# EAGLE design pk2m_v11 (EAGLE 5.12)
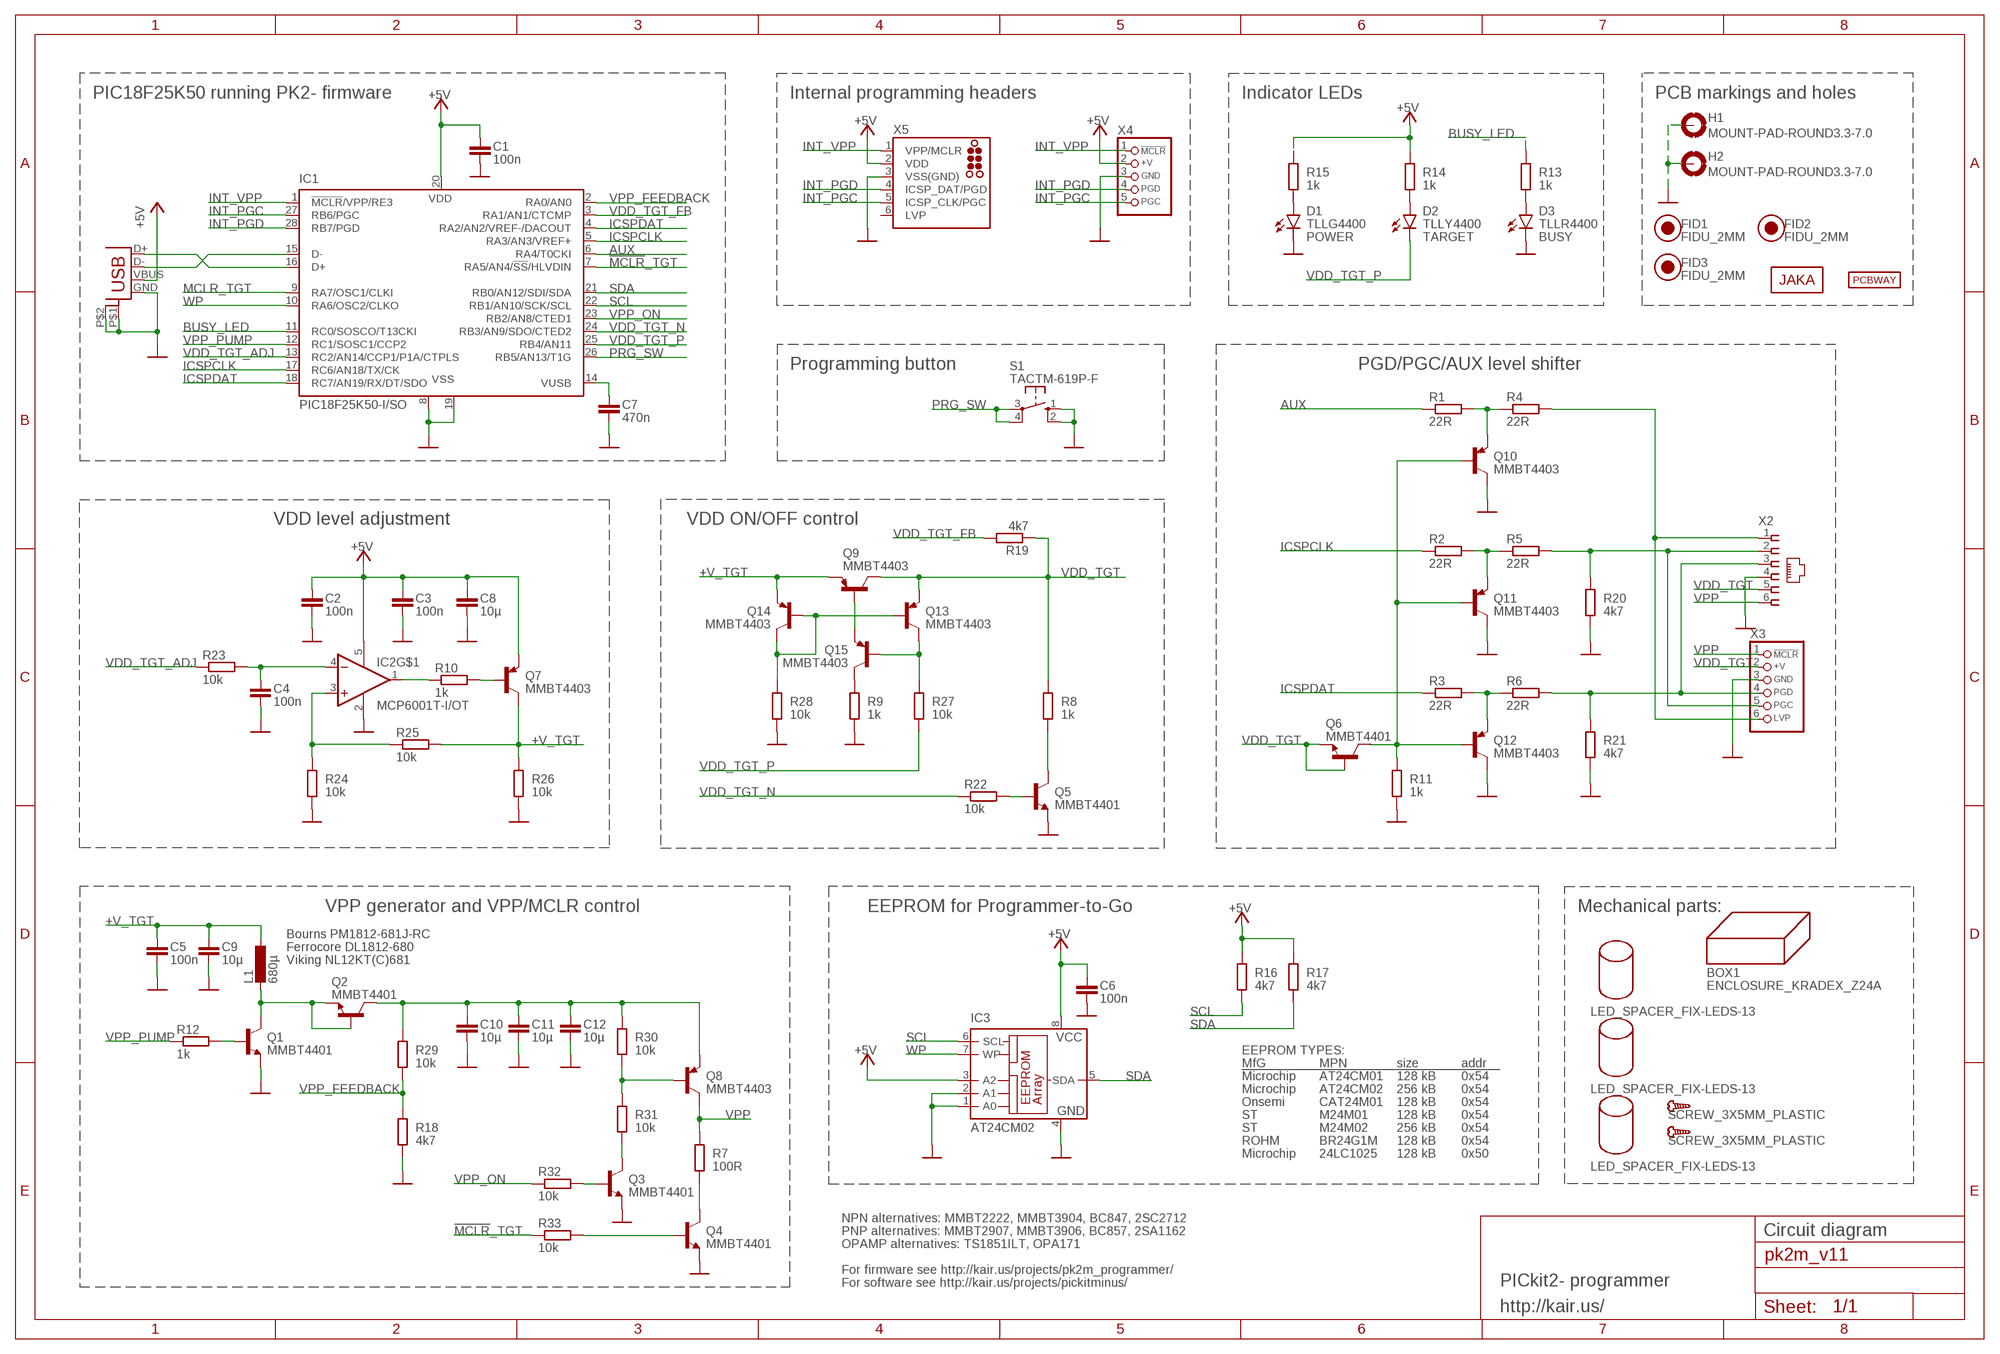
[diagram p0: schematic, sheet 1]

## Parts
BOX1  ENCLOSURE_KRADEX_Z24A  [KRADEX_Z24A]
C1  100n  C-EUC0805  [C0805]
C2  100n  C-EUC0805  [C0805]
C3  100n  C-EUC0805  [C0805]
C4  100n  C-EUC0805  [C0805]
C5  100n  C-EUC0805  [C0805]
C6  100n  C-EUC0805  [C0805]
C7  470n  C-EUC0805  [C0805]
C8  10µ  C-EUC0805  [C0805]
C9  10µ  C-EUC0805  [C0805]
C10  10µ  C-EUC0805  [C0805]
C11  10µ  C-EUC0805  [C0805]
C12  10µ  C-EUC0805  [C0805]
D1  TLLG4400  TLLG4400-LED-GREEN-3MM  [LED3MM]
D2  TLLY4400  TLLY4400-LED-YELLOW-3MM  [LED3MM]
D3  TLLR4400  TLLR4400-LED-RED-3MM  [LED3MM]
FID1  FIDU_2MM  [FIDU_2MM]
FID2  FIDU_2MM  [FIDU_2MM]
FID3  FIDU_2MM  [FIDU_2MM]
H1  MOUNT-PAD-ROUND3.3-7.0  [3,3-PAD-7,0]
H2  MOUNT-PAD-ROUND3.3-7.0  [3,3-PAD-7,0]
IC1  PIC18F25K50-I/SO  PIC18F2XK50-I/SO  [SO28W]
IC2  MCP6001T-I/OT  [SOT23-5]
IC3  AT24CM02  24AA1025T-I/SN  [SO08]
L1  680µ  L-EU_PM1812_BOURNS  [PM1812]
LOGO1  PCBWAY_LOGO_SILK_TINY  [PCBWAY_LOGO_SILK_TINY]
Q1  MMBT4401  MMBT4401LT1-NPN-SOT-23-BEC  [SOT-23]
Q2  MMBT4401  MMBT4401LT1-NPN-SOT-23-BEC  [SOT-23]
Q3  MMBT4401  MMBT4401LT1-NPN-SOT-23-BEC  [SOT-23]
Q4  MMBT4401  MMBT4401LT1-NPN-SOT-23-BEC  [SOT-23]
Q5  MMBT4401  MMBT4401LT1-NPN-SOT-23-BEC  [SOT-23]
Q6  MMBT4401  MMBT4401LT1-NPN-SOT-23-BEC  [SOT-23]
Q7  MMBT4403  MMBT4403LT1-PNP-SOT-23-BEC  [SOT-23]
Q8  MMBT4403  MMBT4403LT1-PNP-SOT-23-BEC  [SOT-23]
Q9  MMBT4403  MMBT4403LT1-PNP-SOT-23-BEC  [SOT-23]
Q10  MMBT4403  MMBT4403LT1-PNP-SOT-23-BEC  [SOT-23]
Q11  MMBT4403  MMBT4403LT1-PNP-SOT-23-BEC  [SOT-23]
Q12  MMBT4403  MMBT4403LT1-PNP-SOT-23-BEC  [SOT-23]
Q13  MMBT4403  MMBT4403LT1-PNP-SOT-23-BEC  [SOT-23]
Q14  MMBT4403  MMBT4403LT1-PNP-SOT-23-BEC  [SOT-23]
Q15  MMBT4403  MMBT4403LT1-PNP-SOT-23-BEC  [SOT-23]
R1  22R  R-EU_R0805  [R0805]
R2  22R  R-EU_R0805  [R0805]
R3  22R  R-EU_R0805  [R0805]
R4  22R  R-EU_R0805  [R0805]
R5  22R  R-EU_R0805  [R0805]
R6  22R  R-EU_R0805  [R0805]
R7  100R  R-EU_R0805  [R0805]
R8  1k  R-EU_R0805  [R0805]
R9  1k  R-EU_R0805  [R0805]
R10  1k  R-EU_R0805  [R0805]
R11  1k  R-EU_R0805  [R0805]
R12  1k  R-EU_R0805  [R0805]
R13  1k  R-EU_R0805  [R0805]
R14  1k  R-EU_R0805  [R0805]
R15  1k  R-EU_R0805  [R0805]
R16  4k7  R-EU_R0805  [R0805]
R17  4k7  R-EU_R0805  [R0805]
R18  4k7  R-EU_R0805  [R0805]
R19  4k7  R-EU_R0805  [R0805]
R20  4k7  R-EU_R0805  [R0805]
R21  4k7  R-EU_R0805  [R0805]
R22  10k  R-EU_R0805  [R0805]
R23  10k  R-EU_R0805  [R0805]
R24  10k  R-EU_R0805  [R0805]
R25  10k  R-EU_R0805  [R0805]
R26  10k  R-EU_R0805  [R0805]
R27  10k  R-EU_R0805  [R0805]
R28  10k  R-EU_R0805  [R0805]
R29  10k  R-EU_R0805  [R0805]
R30  10k  R-EU_R0805  [R0805]
R31  10k  R-EU_R0805  [R0805]
R32  10k  R-EU_R0805  [R0805]
R33  10k  R-EU_R0805  [R0805]
S1  TACTM-619P-F  10-XX  [B3F-10XX]
SPACER1  LED_SPACER_FIX-LEDS-13  [DUMMY]
SPACER2  LED_SPACER_FIX-LEDS-13  [DUMMY]
SPACER3  LED_SPACER_FIX-LEDS-13  [DUMMY]
U$1  JAKA_LOGO_SILK_NANO  [JAKA_SILK_NANO]
U$2  SCREW_3X5MM_PLASTIC  [DUMMY]
U$3  SCREW_3X5MM_PLASTIC  [DUMMY]
X1  USB_B_PTH  [USB-B-PTH]
X2  555165-1  [555165-1]
X3  CON_HEADER_PRG_PIC_W_LVP_ENDMARK  [HEADER_PRG_1X06_STAGGERED_ENDMARK]
X4  CON_HEADER_PRG_PIC_ICSPSTAG  [HEADER_PRG_1X05_STAGGERED]
X5  TC2030-MCP-NL-JKA  [TC2030-MCP-NL-JKA]

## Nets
!MCLR!_TGT: IC1.7(RA5/AN4/!SS!/HLVDIN) R33.1
+5V [power]: C1.1 C2.1 C3.1 C6.1 C8.1 IC1.20(VDD) IC2.5(V+) IC3.3(A2) IC3.8(VCC) Q7.2(E) R14.2 R15.2 R16.2 R17.2 X1.VBUS X4.2(+V) X5.2(VDD)
+V_TGT [power]: C5.1 C9.1 L1.1 Q7.3(C) Q9.2(E) Q14.2(E) R25.2 R26.2
AUX: IC1.6(RA4/T0CKI) R1.1
BUSY_LED: IC1.11(RC0/SOSCO/T13CKI) R13.2
GND [power]: C1.2 C2.2 C3.2 C4.2 C5.2 C6.2 C7.2 C8.2 C9.2 C10.2 C11.2 C12.2 D1.K D3.K H1.B3,3(MOUNT) H2.B3,3(MOUNT) IC1.8(VSS) IC1.19(VSS) IC2.2(V-) IC3.1(A0) IC3.2(A1) IC3.4(GND) Q1.2(E) Q3.2(E) Q4.2(E) Q5.2(E) Q10.3(C) Q11.3(C) Q12.3(C) R9.1 R11.1 R18.1 R20.1 R21.1 R24.1 R26.1 R28.1 S1.1(S) S1.2(S1) X1.GND X1.P$1(SHIELD) X1.P$2(SHIELD1) X2.4 X3.3(GND) X4.3(GND) X5.3(VSS(GND))
ICSPCLK: IC1.5(RA3/AN3/VREF+) IC1.17(RC6/AN18/TX/CK) R2.1
ICSPDAT: IC1.4(RA2/AN2/VREF-/DACOUT) IC1.18(RC7/AN19/RX/DT/SDO) R3.1
INT_PGC: IC1.27(RB6/PGC) X4.5(PGC) X5.5(ICSP_CLK/PGC)
INT_PGD: IC1.28(RB7/PGD) X4.4(PGD) X5.4(ICSP_DAT/PGD)
INT_VPP: IC1.1(!MCLR!/VPP/RE3) X4.1(/MCLR) X5.1(VPP/MCLR)
MCLR_TGT: IC1.9(RA7/OSC1/CLKI)
N$1 [power]: C7.1 IC1.14(VUSB)
N$2: D3.A R13.1
N$3: D2.A R14.1
N$4: D1.A R15.1
N$5: IC2.1(OUT) R10.1
N$6: Q13.1(B) Q14.1(B) Q14.3(C) R28.2
N$7 [USB]: IC1.16(D+) X1.D+
N$8 [USB]: IC1.15(D-) X1.D-
N$9: C4.1 IC2.4(-IN) R23.2
N$10: IC2.3(+IN) R24.2 R25.1
N$11: Q9.1(B) Q15.2(E)
N$12: Q7.1(B) R10.2
N$14: Q5.1(B) R22.2
N$15: Q3.1(B) R32.2
N$16: L1.2 Q1.3(C) Q2.1(B) Q2.2(E)
N$17: Q5.3(C) R8.1
N$18: Q1.1(B) R12.2
N$19: Q4.1(B) R33.2
N$20: Q12.2(E) R3.2 R6.1
N$21: C10.1 C11.1 C12.1 Q2.3(C) Q8.2(E) R29.2 R30.2
N$22: R6.2 R21.2 X2.3 X3.4(PGD)
N$23: Q8.1(B) R30.1 R31.2
N$24: Q4.3(C) R7.1
N$25: Q13.3(C) Q15.1(B) R27.2
N$26: Q3.3(C) R31.1
N$27: Q15.3(C) R9.2
N$28: Q11.2(E) R2.2 R5.1
N$29: R5.2 R20.2 X2.2 X3.5(PGC)
N$30: Q6.3(C) Q10.1(B) Q11.1(B) Q12.1(B) R11.2
N$31: Q10.2(E) R1.2 R4.1
N$32: R4.2 X2.1 X3.6(LVP)
PRG_SW: IC1.26(RB5/AN13/T1G) S1.3(P) S1.4(P1)
SCL: IC1.22(RB1/AN10/SCK/SCL) IC3.6(SCL) R16.1
SDA: IC1.21(RB0/AN12/SDI/SDA) IC3.5(SDA) R17.1
VDD_TGT [power]: Q6.1(B) Q6.2(E) Q9.3(C) Q13.2(E) R8.2 R19.1 X2.5 X3.2(+V)
VDD_TGT_ADJ: IC1.13(RC2/AN14/CCP1/P1A/CTPLS) R23.1
VDD_TGT_FB: IC1.3(RA1/AN1/CTCMP) R19.2
VDD_TGT_N: IC1.24(RB3/AN9/SDO/CTED2) R22.1
VDD_TGT_P: D2.K IC1.25(RB4/AN11) R27.1
VPP: Q8.3(C) R7.2 X2.6 X3.1(/MCLR)
VPP_FEEDBACK: IC1.2(RA0/AN0) R18.2 R29.1
VPP_ON: IC1.23(RB2/AN8/CTED1) R32.1
VPP_PUMP: IC1.12(RC1/SOSC1/CCP2) R12.1
WP: IC1.10(RA6/OSC2/CLKO) IC3.7(WP)
Unconnected: X5.6(LVP)

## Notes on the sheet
- PIC18F25K50 running PK2- firmware | Internal programming headers | Indicator LEDs | PCB markings and holes
- POWER | TARGET | BUSY
- Programming button | PGD/PGC/AUX level shifter
- VDD level adjustment | VDD ON/OFF control
- VPP generator and VPP/MCLR control | EEPROM for Programmer-to-Go | Mechanical parts:
- Bourns PM1812-681J-RC
- Ferrocore DL1812-680
- Viking NL12KT(C)681
- EEPROM TYPES:
- MfG | MPN | size | addr
- Microchip | AT24CM01 | 128 kB | 0x54
- Microchip | AT24CM02 | 256 kB | 0x54
- Onsemi | CAT24M01 | 128 kB | 0x54
- ST | M24M01 | 128 kB | 0x54
- ST | M24M02 | 256 kB | 0x54
- ROHM | BR24G1M | 128 kB | 0x54
- Microchip | 24LC1025 | 128 kB | 0x50
- NPN alternatives: MMBT2222, MMBT3904, BC847, 2SC2712
- PNP alternatives: MMBT2907, MMBT3906, BC857, 2SA1162 | Circuit diagram
- OPAMP alternatives: TS1851ILT, OPA171
- For firmware see http://kair.us/projects/pk2m_programmer/
- For software see http://kair.us/projects/pickitminus/ | PICkit2- programmer
- http://kair.us/

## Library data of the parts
BOX1 = omat:ENCLOSURE
C1-C12 = omat:C-EU: CAPACITOR, European symbol
D1 = omat:*-LED-GREEN-: Green leds in various packages and types
D2 = omat:*-LED-YELLOW-: Yellow leds in various packages and types
D3 = omat:*-LED-RED-: Red leds in varius packages and types
FID1-FID3 = omat:FIDU
H1 H2 = omat:MOUNT-PAD-ROUND: MOUNTING PAD, round
IC1 = omat:PIC18F2XK50
IC2 = omat:MCP6001
IC3 = omat:24*
L1 = omat:L-EU_
LOGO1 = omat:PCBWAY_LOGO
Q1-Q6 = omat:*-NPN-: NPN Transistror
Q7-Q15 = omat:*-PNP-: PNP Transistror
R1-R33 = omat:R-EU_: RESISTOR, European symbol
S1 = omat:10-XX: OMRON SWITCH; MPN: B3F-1000; OC_FARNELL: 176432; OC_NEWARK: 36M3542
SPACER1-SPACER3 = omat:LED_SPACER
U$1 = omat:JAKA_LOGO
U$2 U$3 = omat:SCREW
X1 = omat:USB_B_PTH
X2 = con-amp:555165-1: AMP connector; MF: TYCO ELECTRONICS; MPN: 5555165-1; OC_FARNELL: 1654820; OC_NEWARK: 42K8762
X3 = omat:CON_HEADER_PRG_PIC_W_LVP: 6-pin PIC In Circuit Serial Programming header
X4 = omat:CON_HEADER_PRG_PIC_ICSP: 5-pin PIC In Circuit Serial Programming header
X5 = omat:TC2030: TAG-CONNECT ISP Connector Manufacturer: Tag-Connect Cable for easy In-Circuit PCB Programming. Designed for Microchip ICD2, suitable for many others. Two variants - one "with legs" (for hads-free fit on PCB) and another "without legs" for quick programming. PADDescription 1MCLR/Vpp 2Vdd 3GND 4PGD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

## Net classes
0 default: width 0.25 mm, drill 0.5 mm, clearance 0.2 mm
1 USB: width 0.65 mm, drill 0.5 mm, clearance 0.2 mm
2 power: width 0.5 mm, drill 0.5 mm, clearance 0.2 mm

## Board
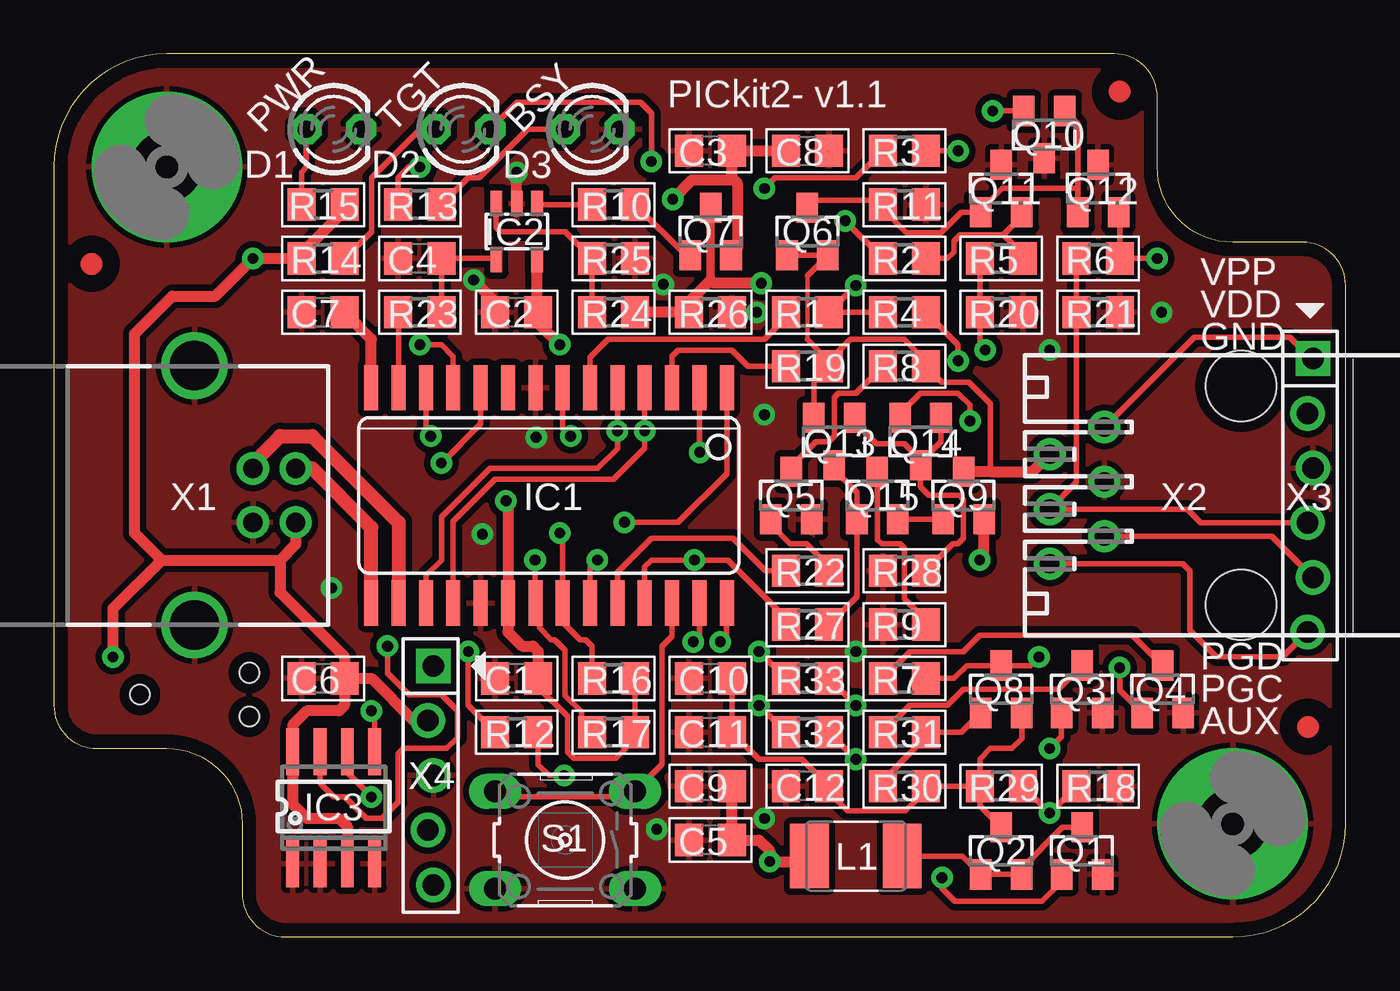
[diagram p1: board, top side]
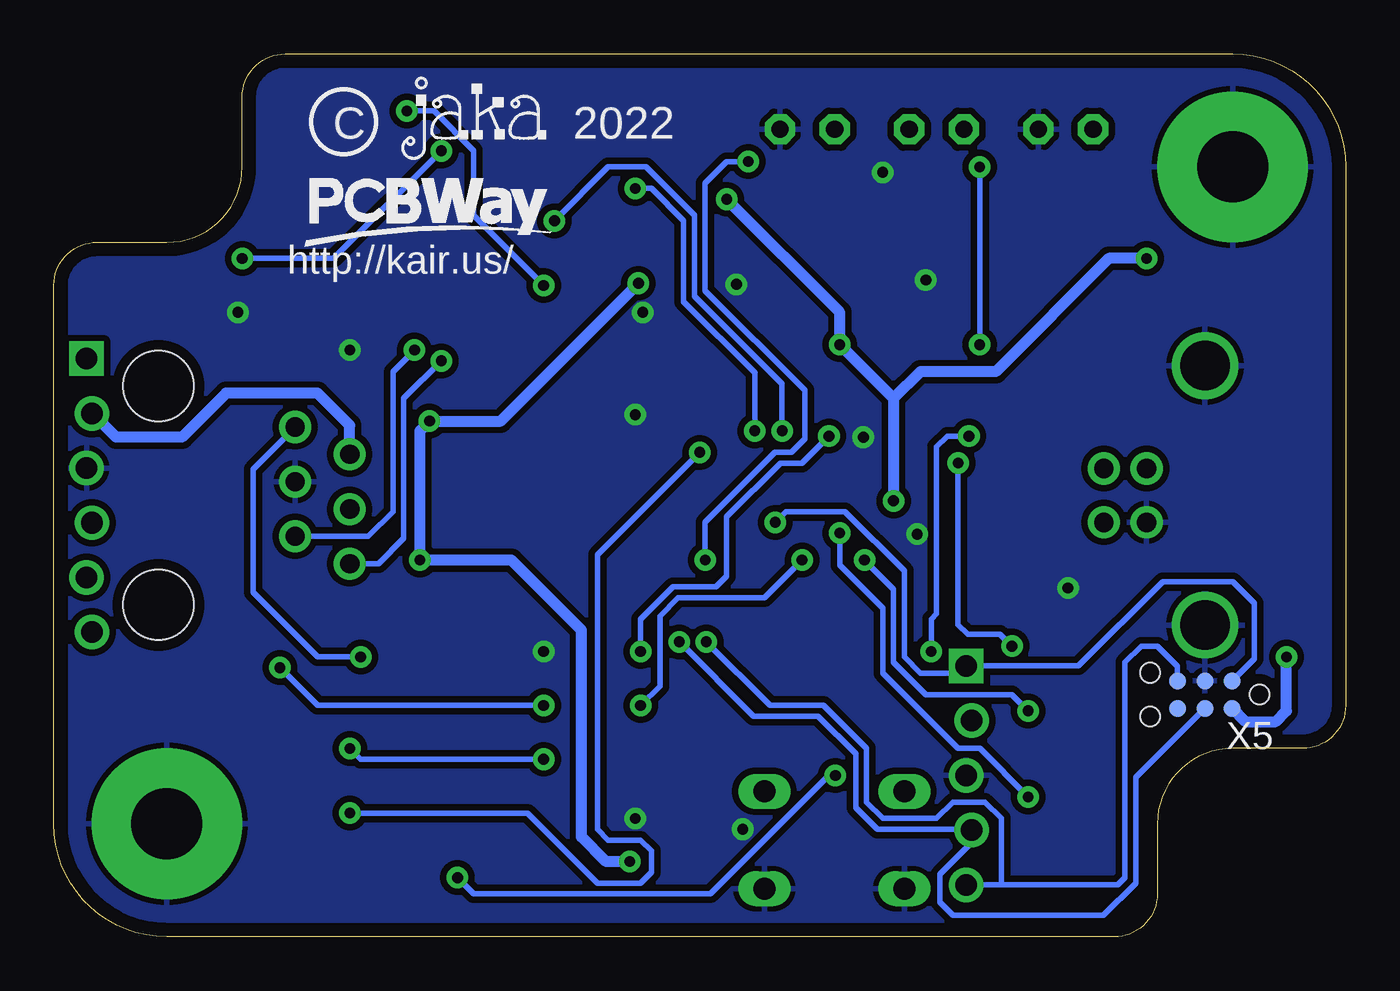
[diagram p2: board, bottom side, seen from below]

Size 60 x 41 mm. Coordinates in mm from the lower left corner, seen from the top.
Copper layers (1*16): Top 0.035mm / dielectric 1.1mm / Bottom 0.035mm
Design rules "j_ace *": minimum track width 0.2mm, minimum drill 0.5mm, track to track 0.25mm, track to pad 0.25mm, pad to pad 0.25mm, via to via 0.25mm, smd to smd 0mil, copper to edge 0.5mm, drill to drill 0.25mm, minimum pad ring 0.3mm, minimum via ring 0.25mm, stop-mask expansion 2mil, vias tented up to drill 100mil, thermal gap 10mil

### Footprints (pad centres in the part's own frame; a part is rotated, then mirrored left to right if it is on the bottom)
C0805 = smd 1.3 x 1.5: 1 -1,0; 2 1,0
LED3MM = drill 0.8 octagon: A -1.27,0; K 1.27,0
3,3-PAD-7,0 = drill 3.3 pad 7 round: B3,3 0,0
SO28W = smd 0.65 x 2.1: 1 -8.255,-5; 2 -6.985,-5; 3 -5.715,-5; 4 -4.445,-5; 5 -3.175,-5; 6 -1.905,-5; 7 -0.635,-5; 8 0.635,-5; 9 1.905,-5; 10 3.175,-5; 11 4.445,-5; 12 5.715,-5; 13 6.985,-5; 14 8.255,-5; 15 8.255,5; 16 6.985,5; 17 5.715,5; 18 4.445,5; 19 3.175,5; 20 1.905,5; 21 0.635,5; 22 -0.635,5; 23 -1.905,5; 24 -3.175,5; 25 -4.445,5; 26 -5.715,5; 27 -6.985,5; 28 -8.255,5
SOT23-5 = smd 0.55 x 1.2: 1 -0.95,-1.3; 2 0,-1.3; 3 0.95,-1.3; 4 0.95,1.3; 5 -0.95,1.3
SO08 = smd 0.6 x 2.2: 1 -1.905,-2.6; 2 -0.635,-2.6; 3 0.635,-2.6; 4 1.905,-2.6; 5 1.905,2.6; 6 0.635,2.6; 7 -0.635,2.6; 8 -1.905,2.6
PM1812 = smd 1.8 x 3: 1 -2.15,0; 2 2.15,0
SOT-23 = smd 1 x 1.4: 1 -0.95,-1.1; 2 0.95,-1.1; 3 0,1.1
R0805 = smd 1.3 x 1.5: 1 -1,0; 2 1,0
B3F-10XX = drill 1.016 long: 1 -3.251,2.261; 2 3.251,2.261; 3 -3.251,-2.261; 4 3.251,-2.261
USB-B-PTH = drill 0.9 round: D+ 0,1.25; D- 1.981,1.25; GND 0,-1.25; VBUS 1.981,-1.25 | drill 2.3 round: P$1 -2.718,-6.02; P$2 -2.718,6.02
555165-1 = drill 0.889 round: 1 -3.175,7.747; 2 -1.905,5.207; 3 -0.635,7.747; 4 0.635,5.207; 5 1.905,7.747; 6 3.175,5.207 | hole 3.251: -5.08,-1.143; 5.08,-1.143
HEADER_PRG_1X06_STAGGERED_ENDMARK = drill 1 square: 1 -6.35,0.127 | drill 1 round: 2 -3.81,-0.127; 3 -1.27,0.127; 4 1.27,-0.127; 5 3.81,0.127; 6 6.35,-0.127
HEADER_PRG_1X05_STAGGERED = drill 1 square: 1 -5.08,0.127 | drill 1 round: 2 -2.54,-0.127; 3 0,0.127; 4 2.54,-0.127; 5 5.08,0.127
TC2030-MCP-NL-JKA = smd 0.787 x 0.787: 1 1.27,-0.635; 2 1.27,0.635; 3 2.54,-0.635; 4 2.54,0.635; 5 3.81,-0.635; 6 3.81,0.635 | hole 0.9: 0,0; 5.08,-1.016; 5.08,1.016

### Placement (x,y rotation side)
BOX1  0,0 0 top
C1  21.5,12 180 top
C2  21.5,29 180 top
C3  30.5,36.5 180 top
C4  17,31.5 180 top
C5  30.5,4.5 180 top
C6  12.5,12 180 top
C7  12.5,29 180 top
C8  35,36.5 0 top
C9  30.5,7 180 top
C10  30.5,12 180 top
C11  30.5,9.5 180 top
C12  35,7 180 top
D1  13,37.5 0 top
D2  19,37.5 0 top
D3  25,37.5 0 top
FID1  1.75,31.25 0 top
FID2  58.25,9.75 0 top
FID3  49.5,39.25 0 top
H1  54.75,5.25 0 top
H2  5.25,35.75 0 top
IC1  23,20.5 180 top
IC2  21.5,32.75 180 top
IC3  13,6 0 top
L1  37.25,3.75 0 top
LOGO1  42.5,33.5 0 bottom
Q1  47.75,4 0 top
Q2  44,4 0 top
Q3  47.75,11.5 0 top
Q4  51.5,11.5 0 top
Q5  34.25,20.5 0 top
Q6  35,32.75 0 top
Q7  30.5,32.75 0 top
Q8  44,11.5 0 top
Q9  42.25,20.5 0 top
Q10  46,37.25 180 top
Q11  44,34.75 0 top
Q12  48.5,34.75 0 top
Q13  36.25,23 180 top
Q14  40.25,23 180 top
Q15  38.25,20.5 0 top
R1  35,29 0 top
R2  39.5,31.5 0 top
R3  39.5,36.5 0 top
R4  39.5,29 0 top
R5  44,31.5 180 top
R6  48.5,31.5 180 top
R7  39.5,12 0 top
R8  39.5,26.5 0 top
R9  39.5,14.5 0 top
R10  26,34 0 top
R11  39.5,34 180 top
R12  21.5,9.5 0 top
R13  17,34 180 top
R14  12.5,31.5 180 top
R15  12.5,34 0 top
R16  26,12 0 top
R17  26,9.5 0 top
R18  48.5,7 180 top
R19  35,26.5 180 top
R20  44,29 180 top
R21  48.5,29 180 top
R22  35,17 0 top
R23  17,29 0 top
R24  26,31.5 180 top
R25  26,29 0 top
R26  30.5,29 180 top
R27  35,14.5 0 top
R28  39.5,17 0 top
R29  44,7 180 top
R30  39.5,7 0 top
R31  39.5,9.5 0 top
R32  35,9.5 0 top
R33  35,12 0 top
S1  23.75,4.5 180 top
SPACER1  19,37.5 0 top
SPACER2  25,37.5 0 top
SPACER3  13,37.5 0 top
U$1  40.5,38 0 bottom
U$2  5.25,35.75 0 top
U$3  54.75,5.25 0 top
X1  9.25,20.5 0 top
X2  54,20.5 90 top
X3  58.35,20.5 270 top
X4  17.5,7.5 270 top
X5  4,11.25 180 bottom

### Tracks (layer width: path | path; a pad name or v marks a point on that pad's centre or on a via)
!MCLR!_TGT  (via drill 0.5)
  Top 0.25: R33.1 v32.75,13.25 | v24,23.25 23.64,23.61 IC1.7
  Bottom 0.25: v24,23.25 25.25,22 26.25,22 28.75,19.5 28.75,16.75 29.25,16.25 31.25,16.25 32.75,14.75 v32.75,13.25
+5V  (via drill 0.5)
  Top 0.25: 22.55,11.95 C1.1 22.5,11.6 23.85,10.25 23.85,8.6 24.15,8.3 26.1,8.3 27,9.2 R17.2 R16.2
  Top 0.5: C1.1 22.5,13.25 22.25,13.5 21.75,13.5 21.09,14.15 IC1.20 21.09,20.16 v21,20.25 | 31.5,35.25 31.75,35 31.75,31.95 Q7.2 31.45,31.7 | 31.5,35.25 C3.1 C8.1 | IC2.5 22.45,29.05 C2.1 22.5,28.5 v23.5,27.5 | X1.VBUS 11.25,19.23 11.25,18.25 10.5,17.5 | 5,17.5 10.5,17.5 | 5,17.5 3.75,18.75 3.75,28 5.5,29.75 7.5,29.75 v9.25,31.5 R14.2 11.5,31.75 13.5,33.75 R15.2 | IC3.3 13.63,5.12 13.25,5.5 11.75,5.5 11.1,6.16 IC3.8 11.1,9.85 11.75,10.5 13.25,10.5 13.5,10.75 C6.1 | 31.5,35.25 31.4,35.15 29.65,35.15 v28.75,34.25 | X4.2 16.71,10.04 14.75,12 C6.1 | C6.1 13.5,13 10.5,16 10.5,17.5 | v2.75,13 2.75,15.25 5,17.5
  Bottom 0.5: 21,25 v23.5,27.5 23.5,29 v28.75,34.25 | 21,25 v21,20.25 | v2.75,13 2.75,10.5 3.25,10 4.66,10 X5.2 | 21,25 19.75,26.25 16.25,26.25 11,31.5 v9.25,31.5
+V_TGT  (via drill 0.5)
  Top 0.25: 39.3,23.8 39.3,24.3 40.25,25.25 42,25.25 42.55,24.7 v42.55,23.95
  Top 0.4: 30.5,30.5 Q7.3
  Top 0.5: v32.85,30.35 30.65,30.35 30.5,30.5 29.5,29.5 R26.2 R25.2 | C9.1 C5.1 32.75,4.5 33.25,4 v33.25,3.5 34.85,3.5 L1.1 | 39.3,23.8 Q14.2 | Q9.2 43.2,17.7 v43,17.5
  Bottom 0.5: v32.85,30.35 39.25,23.95 v42.55,23.95 43,23.5 v43,17.5 38.75,17.5 35.5,14.25 35.5,4.65 34.35,3.5 v33.25,3.5
AUX
  Top 0.25: IC1.6 24.91,26.91 25.75,27.75 33,27.75 34,28.75 R1.1
BUSY_LED  (via drill 0.5)
  Top 0.25: IC1.11 18.55,26.95 18,27.5 v17,27.5 | v17,35.75 16.5,35.75 16,35.25 R13.2
  Bottom 0.25: v17,27.5 v17,35.75
GND  (via drill 0.5)
  Top 0.5: IC2.2 v21.5,35.5 | C2.2 20.5,29.5 v19.5,30.5
  other vias: 46.25,27.25 28.3,30.3 22.4,23.2 19.9,18.7 33,24.25 32.65,29 37.25,13.25 33,5.5 28,5 12.9,16.2 51.45,29
  pour Top (isolate 0.3): 49.25,40.25 arc-90 50.5,39 50.5,35.75 arc90 54.75,31.5 58,31.5 arc-90 59.25,30.25 59.25,5.25 arc-90 54.75,0.75 10.75,0.75 arc-90 9.5,2 9.5,5.25 arc90 5.25,9.5 2,9.5 arc-90 0.75,10.75 0.75,35.75 arc-90 5.25,40.25
  pour Bottom (isolate 0.3): 49.25,40.25 arc-90 50.5,39 50.5,35.75 arc90 54.75,31.5 58,31.5 arc-90 59.25,30.25 59.25,5.25 arc-90 54.75,0.75 10.75,0.75 arc-90 9.5,2 9.5,5.25 arc90 5.25,9.5 2,9.5 arc-90 0.75,10.75 0.75,35.75 arc-90 5.25,40.25
ICSPCLK  (via drill 0.5)
  Top 0.25: v36.75,33.25 R2.1 | IC1.5 v26.18,23.5 26.18,22.68 25.25,21.75 20.25,21.75 18,19.5 18,17.5 17.29,16.79 IC1.17
  Bottom 0.25: v36.75,33.25 34.25,35.75 32.5,35.75 30.25,33.5 30.25,29.75 26.18,25.68 v26.18,23.5
ICSPDAT  (via drill 0.5)
  Top 0.25: IC1.18 18.55,19.3 20.5,21.25 26,21.25 27.45,22.7 v27.45,23.5 IC1.4 | R3.1 37.25,35.25 33.5,35.25 v33,34.75
  Bottom 0.25: v27.45,23.5 27.45,26.2 30.75,29.5 30.75,33.25 32.25,34.75 v33,34.75
INT_PGC  (via drill 0.5)
  Top 0.25: IC1.27 29.98,13.98 v29.7,13.7
  Bottom 0.25: X5.5 7.81,12.56 8.75,13.5 9.5,13.5 10.25,12.75 10.25,2.75 10.58,2.42 16,2.42 | v29.7,13.7 26.75,10.75 24.25,10.75 22.25,8.75 22.25,6.25 21.5,5.5 19,5.5 18.25,6.25 16.75,6.25 16,5.5 16,2.42 | 16,2.42 X4.5
INT_PGD  (via drill 0.5)
  Top 0.25: IC1.28 31.25,14 v30.95,13.7
  Bottom 0.25: v30.95,13.7 27.5,10.25 24.5,10.25 22.75,8.5 22.75,6 21.75,5 17.41,5 X4.4 17.37,4.38 18.85,2.9 18.85,1.6 18.25,1 11.25,1 9.75,2.5 9.75,7.41 X5.4
INT_VPP  (via drill 0.5)
  Top 0.25: IC1.1 31.25,21.5 29,19.25 v26.5,19.25
  Bottom 0.25: X5.1 4.25,12.9 4.25,15.5 5.25,16.5 8.5,16.5 12.42,12.58 X4.1 17.96,12.25 19.75,12.25 20.5,13 20.5,17 23.25,19.75 26,19.75 v26.5,19.25
N$1
  Top 0.5: C7.1 14.74,27.75 IC1.14
N$2
  Top 0.25: R13.1 19.25,35.25 19.75,35.25 22,37.5 D3.A
N$3
  Top 0.25: R14.1 14.75,32.75 14.75,35.25 17,37.5 D2.A
N$4
  Top 0.25: R15.1 11.5,35.5 11.73,35.73 D1.A
N$5
  Top 0.25: R10.1 22.5,34 IC2.1
N$6
  Top 0.25: Q13.1 37.2,23.8 37.3,23.8 38.2,22.9 39.5,22.9 40.25,22.15 Q14.3 | R28.2 41.75,18.25 42,18.25 42.25,18.5 42.25,20.3 42.05,20.5 40.65,20.5 40.25,20.9 Q14.3 | Q14.1 41.2,23 40.25,22.05 Q14.3
N$7
  Top 0.65: IC1.16 16.02,19.23 12,23.25 10.5,23.25 9.25,22 X1.D+
N$8
  Top 0.65: IC1.15 14.74,19 12,21.75 X1.D-
N$9
  Top 0.25: R23.2 C4.1 20.5,31.5 IC2.4
N$10
  Top 0.25: R25.1 R24.2 23.75,32.75 20.75,32.75 20.55,32.95 IC2.3
N$11
  Top 0.25: Q15.2 Q9.1
N$12
  Top 0.25: R10.2 29.35,31.65 Q7.1
N$14
  Top 0.25: Q5.1 33.3,19.15 34.2,18.25 34.95,18.25 36,17.2 R22.2
N$15  (via drill 0.5)
  Top 0.25: Q3.1 46.8,9.3 v46.25,8.75 | R32.2 v37.25,8.25
  Bottom 0.25: v37.25,8.25 45.75,8.25 v46.25,8.75
N$16
  Top 0.25: L1.2 42.2,3.75 Q2.1 Q2.2 44.95,3.2 46.85,5.1 Q1.3
N$17
  Top 0.25: Q5.3 34.25,21.85 35.4,23 36,23 36.25,23.25 36.25,25.05 36.45,25.25 37.25,25.25 R8.1
N$18  (via drill 0.5)
  Top 0.25: R12.2 22.5,8 23,7.5 v23.7,7.5 | Q1.1 46.8,2.55 45.9,1.65 41.85,1.65 41.25,2.25 v41.25,2.75
  Bottom 0.25: v41.25,2.75 40.5,2 29.5,2 24,7.5 v23.7,7.5
N$19  (via drill 0.5)
  Top 0.25: R33.2 v37.25,10.75 | v49.5,12.5 49.5,11.45 Q4.1
  Bottom 0.25: v37.25,10.75 47.75,10.75 v49.5,12.5
N$20  (via drill 0.5)
  Top 0.25: Q12.2 49.5,33.6 R6.1 v51.25,31.5 | R3.2 v42,36.5
  Bottom 0.25: v42,36.5 47,31.5 v51.25,31.5
N$21
  Top 0.25: C10.1 C11.1 32.75,8.25 34.75,8.25 C12.1 36,6.7 36.85,5.85 39.55,5.85 40.15,6.45 40.6,6.45 40.6,6.9 R30.2 R29.2 | Q2.3 43,6.1 R29.2 | Q8.2 44.95,9.2 44.5,8.75 43.5,8.75 43,8.25 R29.2
N$22
  Top 0.25: X3.4 53.27,19.23 52.63,19.86 X2.3 47.5,21.11 R21.2 R6.2
N$23
  Top 0.25: R30.1 38.5,7.25 40,8.75 40,9 R31.2 42.15,9.5 Q8.1
N$24
  Top 0.25: R7.1 39.75,13.25 42.25,13.25 43,14 50.1,14 Q4.3
N$25
  Top 0.25: Q13.3 36.25,21.7 37.3,20.65 Q15.1 37.3,15.8 R27.2
N$26
  Top 0.25: R31.1 39.75,10.75 41.5,10.75 42.25,11.5 46.65,11.5 Q3.3
N$27
  Top 0.25: R9.2 40.5,14.7 39.5,15.7 39.5,18.05 39.3,18.25 38.45,18.25 38.25,18.45 Q15.3
N$28
  Top 0.25: R2.2 41.5,31.5 41.8,31.8 41.8,32.3 42.1,32.6 44.1,32.6 | 44.1,32.6 44.95,33.45 Q11.2 | R5.1 44.5,32 44.5,32.2 44.1,32.6
N$29  (via drill 0.5)
  Top 0.25: X3.5 56.57,18.59 X2.2 | v43.25,27.25 43,27.5 R20.2 R5.2
  Bottom 0.25: X2.2 45.41,18.59 44.25,19.75 44.25,26.25 v43.25,27.25
N$30
  Top 0.25: Q10.1 47.55,37.75 47.55,34.75 | 47.55,34.75 Q12.1 | 47.55,34.75 44.05,34.75 43.05,33.75 Q11.1 42.15,33.65 41.2,32.7 39.6,32.7 38.5,33.8 R11.2 38.2,34 38,34.2 35.35,34.2 Q6.3
N$31  (via drill 0.5)
  Top 0.25: R4.1 R1.2 v37.25,30.25 | v43.6,38.35 Q10.2
  Bottom 0.25: v43.6,38.35 42.35,38.35 40.5,36.5 40.5,33.5 v37.25,30.25
N$32  (via drill 0.5)
  Top 0.25: R4.2 42,27.5 v42,26.75 | X2.1 52.42,17.32 52.75,17 52.75,14.25 54,13 57.07,13 X3.6
  Bottom 0.25: X2.1 44.92,17.32 43.75,18.5 43.75,25 v42,26.75
PRG_SW
  Top 0.25: S1.4 20.76,6.5 26.74,6.5 S1.3 28.25,8.01 28.25,13.5 28.71,13.96 IC1.26
SCL  (via drill 0.5)
  Top 0.25: v23.5,18.75 23.64,18.61 IC1.22 23.64,14.62 24.45,13.8 24.7,13.8 25,13.5 R16.1 | IC3.6 13.63,7.62 v14.75,6.5
  Bottom 0.25: v23.5,18.75 23.5,17.25 21.5,15.25 21.5,12.25 18,8.75 17,8.75 v14.75,6.5
SDA  (via drill 0.5)
  Top 0.25: v22.35,17.5 22.35,15.52 IC1.21 22.55,15.31 22.55,14.35 23.1,13.8 23.25,13.8 23.75,13.3 23.75,11.2 24.5,10.45 24.5,10.1 25,9.6 R17.1 | IC3.5 14.9,10.35 v14.75,10.5
  Bottom 0.25: v14.75,10.5 15.5,11.25 19.5,11.25 21,12.75 21,16.15 v22.35,17.5
VDD_TGT
  Top 0.22: 35,27.75 35,30.7
  Top 0.25: Q6.1 Q6.2 35,30.7 | 35,27.75 35.5,27.25 35.5,27 R19.1 | Q13.2 35.3,25.8 R19.1 | R19.1 36,26.75 37,27.75 39.5,27.75 40,27.25 40,27 R8.2 41.25,25.75 42.5,25.75 43.5,24.75 43.5,21.6
  Top 0.5: Q9.3 43.5,21.6 45.45,21.6 X2.5
  Bottom 0.5: X2.5 46.25,23.75 47.75,25.25 52,25.25 54.05,23.2 57.11,23.2 X3.2
VDD_TGT_ADJ
  Top 0.25: R23.1 16.02,28.98 IC1.13
VDD_TGT_FB
  Top 0.25: R19.2 32.25,26.5 31.5,27.25 29,27.25 28.71,26.96 IC1.3
VDD_TGT_N
  Top 0.25: IC1.24 26.18,16.93 27.75,18.5 31.55,18.5 33.05,17 R22.1
VDD_TGT_P  (via drill 0.5)
  Top 0.25: D2.K 21.52,38.75 27.25,38.75 27.75,38.25 v27.75,36 | IC1.25 27.45,17.2 27.75,17.5 v29.75,17.5 31.3,17.5 34,14.8 R27.1
  Bottom 0.25: v27.75,36 28.75,36 29.75,35 29.75,30 25.12,25.38 25.12,23.12 25.75,22.5 26.5,22.5 29.75,19.25 v29.75,17.5
VPP  (via drill 0.5)
  Top 0.25: R7.2 41.8,12 42.4,12.6 Q8.3 45.35,12.6 v45.75,13 | X3.1 58.4,26.85 57.4,27.85 52.97,27.85 X2.6
  Bottom 0.25: v45.75,13 47.75,13 50.75,16 50.75,21.72 X2.6
VPP_FEEDBACK  (via drill 0.5)
  Top 0.25: R29.1 v46.25,5.75 R18.2 | IC1.2 29.98,22.52 v30,22.5
  Bottom 0.25: v30,22.5 34.75,17.75 34.75,5 34.25,4.5 32.75,4.5 32.25,4 32.25,3 32.75,2.5 34.75,2.5 38,5.75 v46.25,5.75
VPP_ON  (via drill 0.5)
  Top 0.25: v32.75,10.75 R32.1 | v25.25,17.5 24.91,17.16 IC1.23
  Bottom 0.25: v32.75,10.75 31.85,11.65 31.85,14.9 31,15.75 27,15.75 v25.25,17.5
VPP_PUMP  (via drill 0.5)
  Top 0.25: R12.1 19.25,10.75 v19.25,13.25 | v17.5,23.25 17.29,23.46 IC1.12
  Bottom 0.25: v19.25,13.25 19.25,14.75 19,15 19,22.75 18.5,23.25 v17.5,23.25
WP  (via drill 0.5)
  Top 0.25: IC3.7 12.37,7.13 13,6.5 13.5,6.5 14.5,5.5 15.25,5.5 16,6.25 16,8.5 16.25,8.75 18.25,8.75 18.75,9.25 18.75,10.5 18,11.25 16.5,11.25 15.5,12.25 v15.5,13.5 | v18,22 19.82,23.82 IC1.10
  Bottom 0.25: v15.5,13.5 16.05,14.05 17.55,14.05 18,14.5 v18,22

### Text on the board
tPlace: PICkit2- v1.1 | PWR | TGT | BSY | VPP | VDD | GND | PGD | PGC | AUX
bPlace: 2022 | C | http://kair.us/
_tsilk: PICkit2- v1.1 | PWR | TGT | BSY | VPP | VDD | GND | PGD | PGC | AUX
_bsilk: 2022 | C | http://kair.us/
